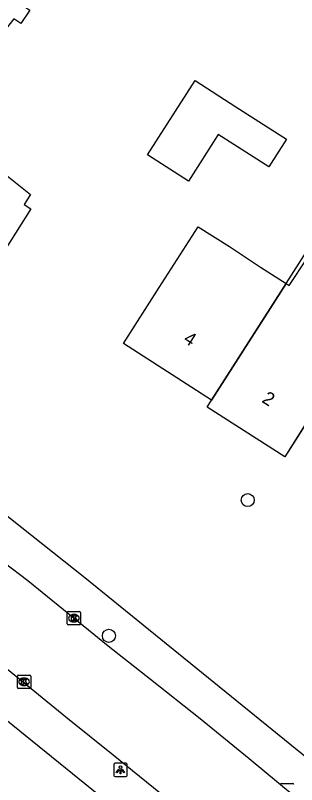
# Model space of a CAD drawing. Extents: x 161141 to 161601, y 381708 to 382245.
# Drawn here: x 161387.6 to 161408.7, y 381911 to 381968.7 of the extents above; entities that cross this region are included whole.
import ezdxf

# ---------------------------------------------------------------- set-up
doc = ezdxf.new("R2010")
doc.units = 0
for name, color, linetype in [('IMGEO_Boom', 7, 'Continuous'), ('IMGEO_Kolk', 7, 'Continuous'), ('IMGEO_Lichtpunt', 7, 'Continuous'), ('IMGEO_Pand', 7, 'Continuous'), ('IMGEO_Pand_nummerreeks', 7, 'Continuous'), ('IMGEO_Pand_vergunning_verleend', 7, 'Continuous'), ('IMGEO_Rijbaan_lokaal_open', 7, 'Continuous'), ('IMGEO_Voetpad_open', 7, 'Continuous')]:
    doc.layers.add(name, color=color, linetype=linetype)

msp = doc.modelspace()

# ---------------------------------------------------------------- linework, layer by layer
at = {"layer": 'IMGEO_Boom'}
for centre in [(161405.049, 381932.349), (161394.629, 381922.175)]:
    msp.add_circle(centre, 0.489, dxfattribs=at)
at = {"layer": 'IMGEO_Kolk'}
for p, q in [((161391.573, 381923.992), (161392.425, 381923.992)), ((161391.498, 381923.066), (161391.498, 381923.918)), ((161391.986, 381923.772), (161392.011, 381923.772)), ((161392.499, 381923.918), (161392.499, 381923.066)), ((161392.425, 381922.992), (161391.573, 381922.992)), ((161392.009, 381923.212), (161391.984, 381923.212)), ((161387.755, 381918.306), (161387.755, 381919.158)), ((161387.83, 381919.232), (161388.682, 381919.232)), ((161388.243, 381919.012), (161388.268, 381919.012)), ((161388.756, 381919.158), (161388.756, 381918.306)), ((161388.682, 381918.232), (161387.83, 381918.232)), ((161388.266, 381918.452), (161388.241, 381918.452)), ((161407.588, 381911.099), (161408.44, 381911.099))]:
    msp.add_line(p, q, dxfattribs=at)
for points in [[(161391.573, 381923.992), (161392.425, 381923.992)], [(161391.498, 381923.066), (161391.498, 381923.918)], [(161391.819, 381923.692), (161391.942, 381923.692), (161391.942, 381923.541), (161392.072, 381923.692), (161392.236, 381923.692), (161392.09, 381923.541), (161392.243, 381923.292), (161392.091, 381923.292), (161392.006, 381923.456), (161391.942, 381923.389), (161391.942, 381923.292), (161391.819, 381923.292), (161391.819, 381923.692)], [(161392.499, 381923.918), (161392.499, 381923.066)], [(161392.425, 381922.992), (161391.573, 381922.992)], [(161387.755, 381918.306), (161387.755, 381919.158)], [(161387.83, 381919.232), (161388.682, 381919.232)], [(161388.076, 381918.932), (161388.199, 381918.932), (161388.199, 381918.781), (161388.329, 381918.932), (161388.493, 381918.932), (161388.347, 381918.781), (161388.5, 381918.532), (161388.348, 381918.532), (161388.263, 381918.696), (161388.199, 381918.629), (161388.199, 381918.532), (161388.076, 381918.532), (161388.076, 381918.932)], [(161388.756, 381919.158), (161388.756, 381918.306)], [(161388.682, 381918.232), (161387.83, 381918.232)], [(161407.588, 381911.099), (161408.44, 381911.099)]]:
    msp.add_lwpolyline(points, dxfattribs=at)
for centre, start, end in [((161391.575, 381923.916), 91.55205, 178.44795), ((161391.575, 381923.916), 91.55205, 178.44795), ((161392.423, 381923.916), 1.55205, 88.44795), ((161392.423, 381923.916), 1.55205, 88.44795), ((161391.575, 381923.068), 181.55205, 268.44795), ((161391.575, 381923.068), 181.55205, 268.44795), ((161392.423, 381923.068), 271.55205, 358.44795), ((161392.423, 381923.068), 271.55205, 358.44795), ((161387.832, 381919.156), 91.55205, 178.44795), ((161387.832, 381919.156), 91.55205, 178.44795), ((161388.68, 381919.156), 1.55205, 88.44795), ((161388.68, 381919.156), 1.55205, 88.44795), ((161387.832, 381918.308), 181.55205, 268.44795), ((161387.832, 381918.308), 181.55205, 268.44795), ((161388.68, 381918.308), 271.55205, 358.44795), ((161388.68, 381918.308), 271.55205, 358.44795), ((161407.59, 381911.023), 91.55205, 178.44795), ((161407.59, 381911.023), 91.55205, 178.44795), ((161408.438, 381911.023), 1.55205, 88.44795), ((161408.438, 381911.023), 1.55205, 88.44795)]:
    msp.add_arc(centre, 0.0765, start, end, dxfattribs=at)
for centre, major_axis, ratio, start_param, end_param in [((161391.985, 381923.492), (-0.387, 0.002), 0.722429, 4.712389, 7.853982), ((161392.01, 381923.492), (-0.39, 0.002), 0.717154, 1.570796, 4.712389), ((161388.242, 381918.732), (-0.387, 0.002), 0.722429, 4.712389, 7.853982), ((161388.267, 381918.732), (-0.39, 0.002), 0.717154, 1.570796, 4.712389)]:
    msp.add_ellipse(centre, major_axis=major_axis, ratio=ratio, start_param=start_param, end_param=end_param, dxfattribs=at)
at = {"layer": 'IMGEO_Lichtpunt'}
for p, q in [((161394.994, 381912.527), (161394.994, 381911.72)), ((161394.994, 381912.527), (161394.994, 381911.72)), ((161395.896, 381912.622), (161395.088, 381912.622)), ((161395.896, 381912.622), (161395.088, 381912.622)), ((161395.99, 381911.72), (161395.99, 381912.527)), ((161395.99, 381911.72), (161395.99, 381912.527)), ((161395.088, 381911.626), (161395.896, 381911.626)), ((161395.088, 381911.626), (161395.896, 381911.626))]:
    msp.add_line(p, q, dxfattribs=at)
for points in [[(161395.368, 381912.191), (161395.407, 381912.163), (161395.219, 381911.901), (161395.181, 381911.928), (161395.368, 381912.191)], [(161395.47, 381912.143), (161395.517, 381912.143), (161395.517, 381911.821), (161395.47, 381911.821), (161395.47, 381912.143)], [(161395.58, 381912.163), (161395.618, 381912.19), (161395.805, 381911.928), (161395.766, 381911.9), (161395.58, 381912.163)]]:
    msp.add_lwpolyline(points, dxfattribs=at)
msp.add_circle((161395.493, 381912.325), 0.0994, dxfattribs=at)
for centre, start, end in [((161395.088, 381912.527), 90, 180), ((161395.088, 381912.527), 90, 180), ((161395.896, 381912.527), 0, 90), ((161395.896, 381912.527), 0, 90), ((161395.088, 381911.72), 180, 270), ((161395.088, 381911.72), 180, 270), ((161395.896, 381911.72), 270, 0), ((161395.896, 381911.72), 270, 360)]:
    msp.add_arc(centre, 0.0946, start, end, dxfattribs=at)
at = {"layer": 'IMGEO_Pand'}
for points in [[(161379.203, 381957.768), (161374.963, 381960.456), (161383.849, 381973.742), (161389.01, 381970.341), (161388.242, 381969.367), (161388.689, 381969.074), (161388.021, 381968.053), (161387.483, 381968.405), (161381.588, 381960.931), (161388.738, 381955.254), (161388.686, 381955.172), (161388.261, 381954.502), (161388.772, 381954.178), (161383.721, 381946.207), (161384.189, 381945.91), (161381.912, 381942.316), (161381.345, 381942.675), (161372.992, 381947.969), (161379.203, 381957.768)], [(161401.095, 381963.786), (161404.162, 381961.827), (161407.953, 381959.405), (161406.629, 381957.331), (161402.837, 381959.753), (161400.602, 381956.254), (161397.535, 381958.213), (161401.095, 381963.786)], [(161402.334, 381939.835), (161395.716, 381944.073), (161398.412, 381948.284), (161401.34, 381952.83), (161403.671, 381951.359), (161406.003, 381949.799), (161407.925, 381948.568)], [(161407.925, 381948.568), (161409.478, 381950.994), (161416.59, 381946.44)], [(161407.925, 381948.568), (161402.334, 381939.835)], [(161419.546, 381944.547), (161419.872, 381944.339), (161416.401, 381938.917), (161411.831, 381941.842), (161410.527, 381939.805), (161407.83, 381935.594), (161402.006, 381939.323), (161402.334, 381939.835)]]:
    msp.add_lwpolyline(points, dxfattribs=at)
at = {"layer": 'IMGEO_Pand_vergunning_verleend'}
msp.add_lwpolyline([(161402.006, 381939.323), (161402.334, 381939.835), (161407.925, 381948.568), (161408.156, 381948.417), (161409.477, 381950.435), (161416.288, 381945.978), (161419.231, 381944.052), (161419.455, 381943.928), (161415.992, 381938.447), (161411.447, 381941.319), (161407.83, 381935.594), (161402.006, 381939.323)], dxfattribs=at)
at = {"layer": 'IMGEO_Rijbaan_lokaal_open'}
for points in [[(161430.53, 381892.26), (161428.93, 381893.541), (161416.582, 381903.762), (161409.42, 381909.443), (161405.146, 381912.95), (161401.483, 381915.955), (161397.742, 381918.904), (161394.58, 381921.397), (161388.533, 381926.301), (161384.971, 381929.006), (161381.728, 381931.469), (161381.315, 381931.756), (161376.383, 381935.18), (161370.251, 381939.135), (161367.432, 381940.939), (161364.318, 381942.933), (161361.946, 381944.451), (161354.44, 381949.434), (161345.5, 381955.194), (161345.132, 381955.433), (161341.968, 381957.49), (161334.965, 381962.043), (161325.373, 381968.263), (161318.237, 381972.89)], [(161426.69, 381887.564), (161425.057, 381888.885), (161404.152, 381905.797), (161399.947, 381909.192), (161394.957, 381913.221), (161391.403, 381916.091), (161386.448, 381920.091)]]:
    msp.add_lwpolyline(points, dxfattribs=at)
at = {"layer": 'IMGEO_Voetpad_open'}
for points in [[(161278.294, 382002.287), (161281.877, 382000), (161299.823, 381988.353), (161310.674, 381981.109), (161322.611, 381973.432), (161322.712, 381973.551), (161378.924, 381936.994), (161385.641, 381932.206), (161392.817, 381926.552), (161429.313, 381896.994)], [(161384.753, 381917.612), (161384.887, 381917.504), (161410.212, 381897.05)]]:
    msp.add_lwpolyline(points, dxfattribs=at)

# ---------------------------------------------------------------- texts
at = {"layer": 'IMGEO_Pand_nummerreeks'}
for s, rotation, p in [('4', 327.36432, (161400.152, 381944.225)), ('2', 327.37005, (161406.044, 381939.731))]:
    msp.add_text(s, height=1, rotation=rotation, dxfattribs=at).set_placement(p)

doc.saveas('drawing.dxf')
